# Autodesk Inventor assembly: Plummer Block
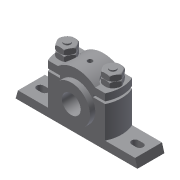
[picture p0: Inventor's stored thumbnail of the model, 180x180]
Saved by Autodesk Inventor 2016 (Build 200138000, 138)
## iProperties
Created: 2011-07
Part Number: Plummer Block
Document SubType Name: Assembly
Designer: CadCim
Author: CadCim
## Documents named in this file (7)
- D:\KAVITA\Autodesk Inventor_ 2016 Project_Kavita\Inventor_Part Files\Inventor_2016_tut\c09_Inv_tut_2016\c09_tut02_inv\Plummer Block\Plummer Block.iam
- D:\KAVITA\Autodesk Inventor_ 2016 Project_Kavita\Inventor_Part Files\Inventor_2016_tut\c09_Inv_tut_2016\c09_tut02_inv\Plummer Block\Casting.ipt
- D:\KAVITA\Autodesk Inventor_ 2016 Project_Kavita\Inventor_Part Files\Inventor_2016_tut\c09_Inv_tut_2016\c09_tut02_inv\Plummer Block\Brasses.ipt
- D:\KAVITA\Autodesk Inventor_ 2016 Project_Kavita\Inventor_Part Files\Inventor_2016_tut\c09_Inv_tut_2016\c09_tut02_inv\Plummer Block\Cap.ipt
- D:\KAVITA\Autodesk Inventor_ 2016 Project_Kavita\Inventor_Part Files\Inventor_2016_tut\c09_Inv_tut_2016\c09_tut02_inv\Plummer Block\Bolt.ipt
- D:\KAVITA\Autodesk Inventor_ 2016 Project_Kavita\Inventor_Part Files\Inventor_2016_tut\c09_Inv_tut_2016\c09_tut02_inv\Plummer Block\Nut.ipt
- D:\KAVITA\Autodesk Inventor_ 2016 Project_Kavita\Inventor_Part Files\Inventor_2016_tut\c09_Inv_tut_2016\c09_tut02_inv\Plummer Block\Lock Nut.ipt
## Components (9 placed, 6 different names)
1. Casting:1 — Mate:1, Mate:2, Insert:1, Insert:2, Angle:1, Angle:2
2. Brasses:1 — Mate:1, Mate:2, Mate:3, Mate:4
3. Cap:1 — Mate:3, Mate:4, Insert:3, Insert:4
4. Bolt:1 — Insert:1, Angle:1
5. Bolt:2 — Insert:2, Angle:2
6. Nut:1 — Insert:3, Insert:6
7. Nut:2 — Insert:4, Insert:5
8. Lock Nut:1 — Insert:6
9. Lock Nut:2 — Insert:5
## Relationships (12: Insert 6, Mate 4, Angle 2)
- Mate:1: Casting:1 ↔ Brasses:1
- Mate:2: Casting:1 ↔ Brasses:1
- Mate:3: Brasses:1 ↔ Cap:1
- Mate:4: Brasses:1 ↔ Cap:1
- Insert:1: Casting:1 ↔ Bolt:1
- Insert:2: Casting:1 ↔ Bolt:2
- Angle:1: Casting:1 ↔ Bolt:1
- Angle:2: Casting:1 ↔ Bolt:2
- Insert:3: Cap:1 ↔ Nut:1
- Insert:4: Cap:1 ↔ Nut:2
- Insert:5: Nut:2 ↔ Lock Nut:2
- Insert:6: Nut:1 ↔ Lock Nut:1
